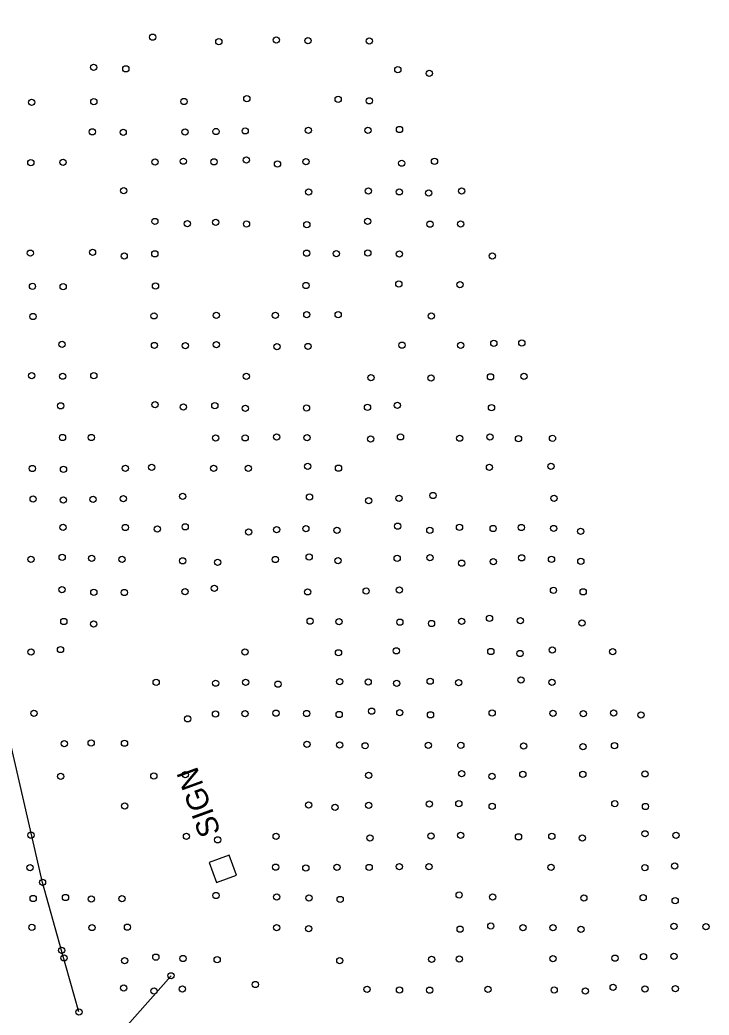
# Model space of a CAD drawing. Extents: x 20503438 to 20508873, y 7964251 to 7984667.
# Drawn here: x 20505729.2 to 20505950.6, y 7977192.3 to 7977511.9 of the extents above; entities that cross this region are included whole.
import ezdxf

# ---------------------------------------------------------------- set-up
doc = ezdxf.new("R2010")
doc.units = 0
for name, color, linetype in [('SurDrainageArrowDown', 7, 'Continuous'), ('SurDrainageArrowUp', 7, 'Continuous'), ('SurPointsNonDTM', 7, 'Continuous'), ('SurRoadPoints', 7, 'Continuous'), ('SurSurveyPoints', 7, 'Continuous')]:
    doc.layers.add(name, color=color, linetype=linetype)

msp = doc.modelspace()

# ---------------------------------------------------------------- linework, layer by layer
at = {"layer": 'SurDrainageArrowDown'}
msp.add_lwpolyline([(20505748.21, 7977193.29), (20505742.63, 7977213.06), (20505736.52, 7977234.9), (20505725.99, 7977280.52), (20505713.88, 7977327.5), (20505706.79, 7977347.37), (20505703.26, 7977372.92), (20505698.22, 7977399.33), (20505687.89, 7977446.43), (20505678.89, 7977496.64), (20505669.89, 7977547.69), (20505664.57, 7977573.19), (20505657.6, 7977599.18), (20505657.57, 7977623.02), (20505649.94, 7977631.12), (20505646.7, 7977632.62), (20505643.09, 7977632.08)], dxfattribs=at)
at = {"layer": 'SurDrainageArrowUp'}
msp.add_lwpolyline([(20505763.74, 7977188.93), (20505777.8, 7977204.89)], dxfattribs=at)
at = {"layer": 'SurPointsNonDTM'}
for centre in [(20505783.16, 7977287.42), (20505792.78, 7977248.54), (20505804.83, 7977202.1)]:
    msp.add_circle(centre, 1, dxfattribs=at)
at = {"layer": 'SurRoadPoints'}
msp.add_lwpolyline([(20505797.6, 7977240.45), (20505797.6, 7977240.45), (20505796.42, 7977243.66), (20505789.99, 7977241.31), (20505792.34, 7977234.88), (20505798.77, 7977237.23), (20505797.6, 7977240.44)], dxfattribs=at)
at = {"layer": 'SurSurveyPoints'}
for centre in [(20505771.91, 7977506.32), (20505811.6, 7977505.43), (20505793.13, 7977504.88), (20505821.77, 7977505.21), (20505841.47, 7977505.08), (20505752.91, 7977496.62), (20505763.28, 7977496.16), (20505850.63, 7977495.9), (20505860.75, 7977494.69), (20505802.13, 7977486.59), (20505831.48, 7977486.39), (20505732.99, 7977485.43), (20505753, 7977485.62), (20505781.96, 7977485.66), (20505841.46, 7977485.88), (20505851.16, 7977476.67), (20505752.48, 7977475.92), (20505762.43, 7977475.78), (20505782.29, 7977475.86), (20505792.26, 7977476.02), (20505801.61, 7977476.23), (20505821.89, 7977476.37), (20505841.02, 7977476.41), (20505732.76, 7977466.03), (20505743.12, 7977466.1), (20505772.65, 7977466.25), (20505781.77, 7977466.49), (20505791.59, 7977466.3), (20505801.99, 7977466.85), (20505811.98, 7977465.6), (20505821.13, 7977466.36), (20505851.9, 7977465.85), (20505862.4, 7977466.47), (20505762.58, 7977457.03), (20505821.97, 7977456.63), (20505841.16, 7977456.94), (20505851.08, 7977456.64), (20505860.54, 7977456.28), (20505871.13, 7977456.92), (20505772.6, 7977447.14), (20505783.04, 7977446.4), (20505792.15, 7977446.89), (20505802.04, 7977446.34), (20505821.4, 7977446.09), (20505840.94, 7977447.2), (20505860.96, 7977446.27), (20505870.78, 7977446.31), (20505732.62, 7977436.97), (20505752.58, 7977437.24), (20505762.75, 7977436.02), (20505772.58, 7977436.74), (20505821.33, 7977436.96), (20505830.87, 7977436.82), (20505840.99, 7977437), (20505851.12, 7977436.72), (20505880.96, 7977436.08), (20505733.28, 7977426.3), (20505743.15, 7977426.2), (20505772.79, 7977426.45), (20505821.13, 7977426.58), (20505850.95, 7977427.03), (20505870.6, 7977426.81), (20505733.42, 7977416.62), (20505772.32, 7977416.82), (20505792.32, 7977416.98), (20505811.32, 7977416.98), (20505821.39, 7977417.24), (20505831.46, 7977417.21), (20505861.39, 7977416.81), (20505742.77, 7977407.69), (20505772.46, 7977407.32), (20505782.4, 7977407.23), (20505792.35, 7977407.56), (20505811.82, 7977406.93), (20505821.77, 7977407), (20505851.96, 7977407.42), (20505870.83, 7977407.39), (20505881.47, 7977407.98), (20505890.46, 7977408.09), (20505733.05, 7977397.59), (20505743.01, 7977397.44), (20505752.99, 7977397.63), (20505801.96, 7977397.43), (20505841.98, 7977396.98), (20505861.32, 7977396.9), (20505880.4, 7977397.25), (20505891.13, 7977397.42), (20505742.33, 7977387.93), (20505772.67, 7977388.34), (20505781.76, 7977387.53), (20505791.86, 7977387.98), (20505801.67, 7977387.15), (20505821.31, 7977387.23), (20505840.88, 7977387.46), (20505850.5, 7977388.07), (20505880.71, 7977387.34), (20505742.94, 7977377.75), (20505752.2, 7977377.77), (20505792.09, 7977377.57), (20505801.59, 7977377.64), (20505811.7, 7977377.9), (20505821.47, 7977377.72), (20505851.48, 7977377.96), (20505880.21, 7977377.9), (20505841.89, 7977377.3), (20505870.46, 7977377.53), (20505889.4, 7977377.4), (20505900.3, 7977377.52), (20505771.6, 7977368.21), (20505821.7, 7977368.5), (20505880.06, 7977368.16), (20505899.8, 7977368.47), (20505733.21, 7977367.81), (20505743.24, 7977367.57), (20505763.13, 7977367.84), (20505791.45, 7977367.87), (20505802.58, 7977367.89), (20505831.57, 7977367.91), (20505781.53, 7977358.84), (20505822.27, 7977358.66), (20505861.94, 7977359.14), (20505733.49, 7977358.01), (20505743.2, 7977357.72), (20505752.74, 7977357.91), (20505762.47, 7977358.11), (20505841.28, 7977357.45), (20505851.02, 7977358.19), (20505900.81, 7977358.19), (20505743.12, 7977348.93), (20505763.11, 7977348.86), (20505782.34, 7977349.07), (20505850.59, 7977349.28), (20505870.45, 7977348.88), (20505890.32, 7977348.85), (20505773.42, 7977348.36), (20505802.69, 7977347.39), (20505811.71, 7977348.19), (20505821.1, 7977348.51), (20505831.06, 7977347.93), (20505860.92, 7977347.93), (20505881.24, 7977348.53), (20505900.72, 7977348.55), (20505909.35, 7977347.6), (20505742.83, 7977339.29), (20505822.15, 7977339.35), (20505732.79, 7977338.63), (20505752.3, 7977338.94), (20505762.04, 7977338.65), (20505781.5, 7977338.15), (20505792.73, 7977337.69), (20505811.31, 7977338.57), (20505831.43, 7977338.17), (20505850.43, 7977338.94), (20505860.96, 7977339.17), (20505871.11, 7977337.41), (20505881.29, 7977337.91), (20505890.39, 7977339.11), (20505899.99, 7977338.61), (20505909.41, 7977338.01), (20505742.74, 7977328.88), (20505753, 7977328.06), (20505762.76, 7977327.97), (20505782.3, 7977328.28), (20505791.7, 7977329.34), (20505821.65, 7977328.18), (20505840.45, 7977328.47), (20505851.14, 7977328.82), (20505900.62, 7977328.67), (20505910.16, 7977328.2), (20505743.36, 7977318.67), (20505752.92, 7977317.83), (20505822.46, 7977318.77), (20505831.76, 7977318.64), (20505851.29, 7977318.46), (20505861.46, 7977318.03), (20505871.13, 7977318.7), (20505880.08, 7977319.71), (20505889.98, 7977318.93), (20505909.78, 7977318.21), (20505732.84, 7977308.9), (20505742.28, 7977309.66), (20505801.51, 7977308.87), (20505831.57, 7977308.62), (20505850.12, 7977309.24), (20505880.51, 7977309.04), (20505889.87, 7977308.4), (20505900.23, 7977309.52), (20505919.64, 7977308.95), (20505773.02, 7977299.1), (20505792.12, 7977298.85), (20505801.73, 7977299.16), (20505812.11, 7977298.55), (20505831.98, 7977299.35), (20505841.12, 7977299.25), (20505850.29, 7977298.8), (20505861.01, 7977299.49), (20505870.14, 7977298.99), (20505890.17, 7977299.86), (20505900.12, 7977299.16), (20505733.74, 7977289.15), (20505792.07, 7977288.98), (20505801.55, 7977289.09), (20505811.52, 7977289.24), (20505821.36, 7977289.12), (20505831.78, 7977288.81), (20505842.23, 7977289.88), (20505851.26, 7977289.42), (20505861.13, 7977288.69), (20505880.93, 7977289.31), (20505900.46, 7977289.17), (20505910.18, 7977289.09), (20505919.95, 7977289.28), (20505928.73, 7977288.63), (20505743.5, 7977279.41), (20505752.14, 7977279.64), (20505762.84, 7977279.58), (20505821.44, 7977279.2), (20505831.94, 7977279), (20505840.13, 7977278.75), (20505860.4, 7977278.92), (20505870.88, 7977278.88), (20505891.05, 7977278.68), (20505910.09, 7977278.5), (20505920.22, 7977278.82), (20505742.34, 7977268.91), (20505772.27, 7977269.08), (20505782.37, 7977269.49), (20505841.26, 7977269.25), (20505871.1, 7977269.78), (20505880.91, 7977268.96), (20505890.79, 7977269.6), (20505910.05, 7977269.57), (20505930.03, 7977269.73), (20505762.91, 7977259.45), (20505821.97, 7977259.71), (20505841.27, 7977259.65), (20505860.77, 7977260.03), (20505870.22, 7977260.15), (20505880.93, 7977259.34), (20505920.32, 7977260.13), (20505830.47, 7977259.01), (20505930.17, 7977259.25), (20505732.84, 7977250.06), (20505861.29, 7977249.8), (20505870.8, 7977250), (20505930.05, 7977250.49), (20505940.01, 7977249.98), (20505782.74, 7977249.69), (20505811.54, 7977249.67), (20505841.68, 7977249.13), (20505889.4, 7977249.51), (20505900.09, 7977249.69), (20505909.87, 7977249.15), (20505939.57, 7977240.12), (20505732.5, 7977239.61), (20505811.37, 7977239.78), (20505821.08, 7977239.52), (20505831.07, 7977239.71), (20505841.42, 7977239.68), (20505851.15, 7977239.96), (20505860.63, 7977239.95), (20505899.83, 7977239.71), (20505929.98, 7977239.58), (20505736.52, 7977234.9), (20505792.26, 7977230.67), (20505870.32, 7977230.83), (20505733.5, 7977229.71), (20505743.88, 7977230.02), (20505752.16, 7977229.53), (20505762.03, 7977229.68), (20505811.73, 7977230.22), (20505822.07, 7977229.85), (20505832.12, 7977229.4), (20505881.06, 7977230.22), (20505910.39, 7977229.89), (20505929.43, 7977229.97), (20505939.71, 7977229.05), (20505733.09, 7977220.46), (20505752.43, 7977220.38), (20505763.79, 7977220.51), (20505811.7, 7977220.33), (20505822.02, 7977220.05), (20505870.64, 7977219.86), (20505880.49, 7977220.87), (20505890.83, 7977220.33), (20505900.46, 7977220.35), (20505909.43, 7977219.82), (20505939.33, 7977220.74), (20505949.61, 7977220.7), (20505742.63, 7977213.06), (20505743.41, 7977210.59), (20505762.86, 7977209.78), (20505772.9, 7977210.88), (20505781.63, 7977210.44), (20505792.61, 7977210.1), (20505831.99, 7977209.77), (20505861.48, 7977210.14), (20505870.36, 7977210.26), (20505900.46, 7977210.36), (20505920.36, 7977210.55), (20505929.54, 7977211), (20505939.33, 7977211.11), (20505777.8, 7977204.89), (20505762.58, 7977200.94), (20505772.35, 7977200.02), (20505781.42, 7977200.62), (20505840.76, 7977200.52), (20505851.18, 7977200.36), (20505860.88, 7977200.26), (20505879.58, 7977200.55), (20505900.86, 7977200.31), (20505910.88, 7977199.98), (20505919.78, 7977201.18), (20505930, 7977200.63), (20505939.78, 7977200.76), (20505748.21, 7977193.29)]:
    msp.add_circle(centre, 1, dxfattribs=at)

# ---------------------------------------------------------------- texts
at = {"layer": 'SurRoadPoints'}
msp.add_text('SIGN', height=6.995, rotation=110.0461, dxfattribs=at).set_placement((20505793.82, 7977251))

doc.saveas('drawing.dxf')
